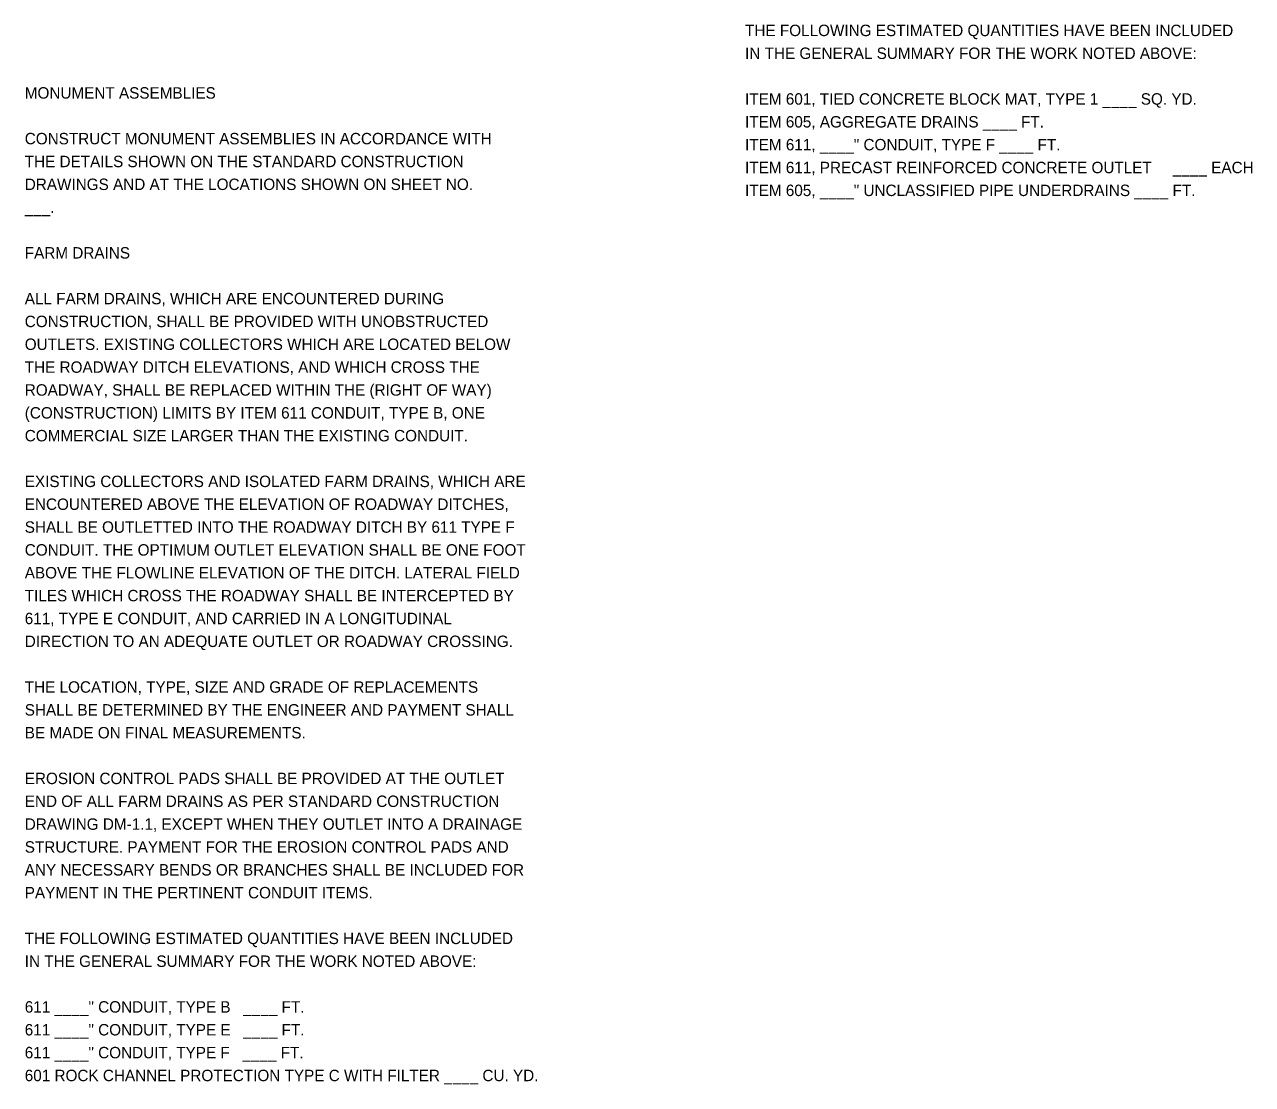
# Model space of a CAD drawing. Extents: x -14.3 to 49.6, y -18.9 to 35.3.
# Drawn here: x 34.55 to 49.59, y -13.46 to -0.47 of the extents above; entities that cross this region are included whole.
import ezdxf

# ---------------------------------------------------------------- set-up
doc = ezdxf.new("R2010")
doc.units = 0
doc.layers.add('SH_Text', color=7, linetype='Continuous')

msp = doc.modelspace()

# ---------------------------------------------------------------- texts
at = {"layer": 'SH_Text'}
for s, p in [('THE FOLLOWING ESTIMATED QUANTITIES HAVE BEEN INCLUDED', (43.373, -0.613)), ('IN THE GENERAL SUMMARY FOR THE WORK NOTED ABOVE:', (43.373, -0.893)), ('MONUMENT ASSEMBLIES', (34.548, -1.379)), ('ITEM 601, TIED CONCRETE BLOCK MAT, TYPE 1 ____ SQ. YD.', (43.373, -1.453)), ('ITEM 605, AGGREGATE DRAINS ____ FT.', (43.373, -1.733)), ('CONSTRUCT MONUMENT ASSEMBLIES IN ACCORDANCE WITH', (34.548, -1.939)), ('ITEM 611, ____" CONDUIT, TYPE F ____ FT.', (43.373, -2.013)), ('THE DETAILS SHOWN ON THE STANDARD CONSTRUCTION', (34.548, -2.219)), ('ITEM 611, PRECAST REINFORCED CONCRETE OUTLET     ____ EACH', (43.373, -2.293)), ('DRAWINGS AND AT THE LOCATIONS SHOWN ON SHEET NO.', (34.548, -2.499)), ('ITEM 605, ____" UNCLASSIFIED PIPE UNDERDRAINS ____ FT.', (43.373, -2.573)), ('___.', (34.548, -2.779)), ('FARM DRAINS', (34.548, -3.339)), ('ALL FARM DRAINS, WHICH ARE ENCOUNTERED DURING', (34.548, -3.899)), ('CONSTRUCTION, SHALL BE PROVIDED WITH UNOBSTRUCTED', (34.548, -4.179)), ('OUTLETS. EXISTING COLLECTORS WHICH ARE LOCATED BELOW', (34.548, -4.459)), ('THE ROADWAY DITCH ELEVATIONS, AND WHICH CROSS THE', (34.548, -4.739)), ('ROADWAY, SHALL BE REPLACED WITHIN THE (RIGHT OF WAY)', (34.548, -5.019)), ('(CONSTRUCTION) LIMITS BY ITEM 611 CONDUIT, TYPE B, ONE', (34.548, -5.299)), ('COMMERCIAL SIZE LARGER THAN THE EXISTING CONDUIT.', (34.548, -5.579)), ('EXISTING COLLECTORS AND ISOLATED FARM DRAINS, WHICH ARE', (34.548, -6.139)), ('ENCOUNTERED ABOVE THE ELEVATION OF ROADWAY DITCHES,', (34.548, -6.419)), ('SHALL BE OUTLETTED INTO THE ROADWAY DITCH BY 611 TYPE F', (34.548, -6.699)), ('CONDUIT. THE OPTIMUM OUTLET ELEVATION SHALL BE ONE FOOT', (34.548, -6.979)), ('ABOVE THE FLOWLINE ELEVATION OF THE DITCH. LATERAL FIELD', (34.548, -7.259)), ('TILES WHICH CROSS THE ROADWAY SHALL BE INTERCEPTED BY', (34.548, -7.539)), ('611, TYPE E CONDUIT, AND CARRIED IN A LONGITUDINAL', (34.548, -7.819)), ('DIRECTION TO AN ADEQUATE OUTLET OR ROADWAY CROSSING.', (34.548, -8.099)), ('THE LOCATION, TYPE, SIZE AND GRADE OF REPLACEMENTS', (34.548, -8.659)), ('SHALL BE DETERMINED BY THE ENGINEER AND PAYMENT SHALL', (34.548, -8.939)), ('BE MADE ON FINAL MEASUREMENTS.', (34.548, -9.219)), ('EROSION CONTROL PADS SHALL BE PROVIDED AT THE OUTLET', (34.548, -9.779)), ('END OF ALL FARM DRAINS AS PER STANDARD CONSTRUCTION', (34.548, -10.059)), ('DRAWING DM-1.1, EXCEPT WHEN THEY OUTLET INTO A DRAINAGE', (34.548, -10.339)), ('STRUCTURE. PAYMENT FOR THE EROSION CONTROL PADS AND', (34.548, -10.619)), ('ANY NECESSARY BENDS OR BRANCHES SHALL BE INCLUDED FOR', (34.548, -10.899)), ('PAYMENT IN THE PERTINENT CONDUIT ITEMS.', (34.548, -11.179)), ('THE FOLLOWING ESTIMATED QUANTITIES HAVE BEEN INCLUDED', (34.548, -11.739)), ('IN THE GENERAL SUMMARY FOR THE WORK NOTED ABOVE:', (34.548, -12.019)), ('611 ____" CONDUIT, TYPE B   ____ FT.', (34.548, -12.579)), ('611 ____" CONDUIT, TYPE E   ____ FT.', (34.548, -12.859)), ('611 ____" CONDUIT, TYPE F   ____ FT.', (34.548, -13.139)), ('601 ROCK CHANNEL PROTECTION TYPE C WITH FILTER ____ CU. YD.', (34.548, -13.419))]:
    msp.add_text(s, height=0.14, dxfattribs=at).set_placement(p)

doc.saveas('drawing.dxf')
